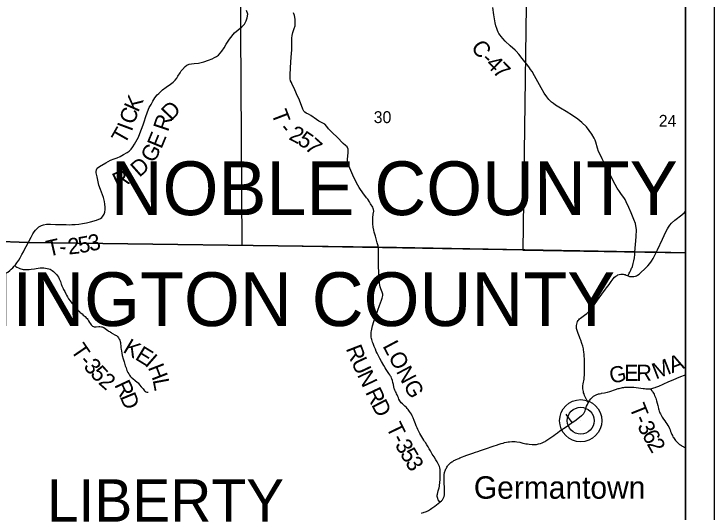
# Model space of a CAD drawing. Extents: x 0 to 34, y 0 to 22.
# Drawn here: x 6.533 to 9, y 15.933 to 17.691 of the extents above; entities that cross this region are included whole.
import ezdxf

# ---------------------------------------------------------------- set-up
doc = ezdxf.new("R2010")
doc.units = 0
for name, color, linetype in [('GM_X_Corporation', 7, 'Continuous'), ('GM_X_County_Road', 7, 'Continuous'), ('GM_X_County_Road_Text', 7, 'Continuous'), ('GM_X_County_Text', 7, 'Continuous'), ('GM_X_Section_Text', 7, 'Continuous'), ('GM_X_Township_Road', 7, 'Continuous'), ('GM_X_Township_Road_Text', 7, 'Continuous'), ('GM_X_Township_Text', 7, 'Continuous'), ('GM_X_Unincorporated', 7, 'Continuous'), ('GM_X_Unincorporated_Location', 7, 'Continuous'), ('GM_X_Unincorporated_Text', 7, 'Continuous'), ('SH_Data', 7, 'Continuous')]:
    doc.layers.add(name, color=color, linetype=linetype)

msp = doc.modelspace()

# ---------------------------------------------------------------- linework, layer by layer
at = {"layer": 'GM_X_Corporation'}
for points in [[(8.3394, 17.8082), (8.3265, 16.8592), (7.3376, 16.8759), (7.332, 17.8222)], [(8.9, 16.8493), (8.9, 17.8023), (8.3394, 17.8082), (8.3265, 16.8592)]]:
    msp.add_lwpolyline(points, close=True, dxfattribs=at)
msp.add_lwpolyline([(8.9, 14.1), (8.9, 16.8499), (8.7964, 16.8516), (8.7214, 16.8529), (7.8171, 16.8691), (6.5825, 16.8858), (6.4571, 16.891), (6.4525, 17.3965), (6.1753, 17.3961), (5.7441, 17.4015), (5.3204, 17.3974), (4.9935, 17.4026), (4.6584, 17.4085), (4.4004, 17.4134)], dxfattribs=at)
at = {"layer": 'GM_X_County_Road'}
for points in [[(8.7216, 16.8524), (8.7258, 16.9063), (8.7264, 16.9317), (8.725, 16.9446), (8.7232, 16.9525), (8.7179, 16.9677), (8.7082, 16.9904), (8.6997, 17.0094), (8.691, 17.0299), (8.6866, 17.0377), (8.6819, 17.0444), (8.6737, 17.0557), (8.6668, 17.0657), (8.6593, 17.0778), (8.6522, 17.0906), (8.6227, 17.148), (8.6152, 17.1626), (8.6057, 17.1811), (8.5984, 17.1957), (8.5935, 17.2066), (8.5899, 17.2183), (8.5834, 17.2399), (8.5809, 17.247), (8.5776, 17.2534), (8.5696, 17.2681), (8.5606, 17.2813), (8.5507, 17.2934), (8.5346, 17.3091), (8.5197, 17.3212), (8.5013, 17.3335), (8.4793, 17.3472), (8.4585, 17.3599), (8.4411, 17.3705), (8.4342, 17.3757), (8.4278, 17.381), (8.4181, 17.3905), (8.4104, 17.3998), (8.4014, 17.4124), (8.3909, 17.4307), (8.3669, 17.4735), (8.3593, 17.4883), (8.3537, 17.4958), (8.3495, 17.5019), (8.3439, 17.5093), (8.3399, 17.5149), (8.3337, 17.5225), (8.3242, 17.5347), (8.3121, 17.5497), (8.3031, 17.5603), (8.2995, 17.5641), (8.2813, 17.5797), (8.2645, 17.5953), (8.2554, 17.6051), (8.2496, 17.6115), (8.246, 17.6166), (8.2423, 17.6228), (8.24, 17.627), (8.2368, 17.6337), (8.2343, 17.6397), (8.2313, 17.6493), (8.2287, 17.6602), (8.2263, 17.674), (8.2241, 17.6888), (8.2208, 17.7147)], [(8.7966, 16.8511), (8.8009, 16.8597), (8.8183, 16.8978), (8.8307, 16.9239), (8.8357, 16.9339), (8.8391, 16.9396), (8.844, 16.9469), (8.8502, 16.9541), (8.8619, 16.9647), (8.8868, 16.984), (8.8955, 16.9915), (8.9, 16.9965)], [(8.6973, 16.7684), (8.6977, 16.7693), (8.7016, 16.7783), (8.7031, 16.7819), (8.7053, 16.7865), (8.7066, 16.7891), (8.7083, 16.7922), (8.7098, 16.7951), (8.7111, 16.7976), (8.7125, 16.8013), (8.7133, 16.8035), (8.714, 16.8059), (8.7157, 16.8118), (8.718, 16.8221), (8.7197, 16.8325), (8.7207, 16.8436), (8.7216, 16.8524)], [(8.6973, 16.7684), (8.7027, 16.7669), (8.7081, 16.7662), (8.7136, 16.7661), (8.7178, 16.7665), (8.7231, 16.7677), (8.7271, 16.7691), (8.7303, 16.7708), (8.7358, 16.7747), (8.7424, 16.7802), (8.7564, 16.7934), (8.7663, 16.8036), (8.7739, 16.8125), (8.7794, 16.82), (8.7857, 16.8299), (8.7917, 16.8414), (8.7966, 16.8511)], [(8.5568, 16.3217), (8.5551, 16.3242), (8.5518, 16.3301), (8.5479, 16.3373), (8.546, 16.3418), (8.544, 16.3467), (8.5421, 16.3524), (8.5407, 16.3569), (8.5396, 16.3612), (8.5387, 16.3654), (8.538, 16.3708), (8.538, 16.376), (8.5382, 16.3816), (8.5391, 16.3885), (8.5419, 16.405), (8.5428, 16.4111), (8.5433, 16.4173), (8.5436, 16.4227), (8.544, 16.4284), (8.5441, 16.4445), (8.5433, 16.4712), (8.5424, 16.4904), (8.5413, 16.5015), (8.5406, 16.507), (8.5397, 16.5118), (8.5387, 16.516), (8.5376, 16.5208), (8.5348, 16.5297), (8.5302, 16.5418), (8.528, 16.5471), (8.5255, 16.5533), (8.5209, 16.5655), (8.5174, 16.5762), (8.5159, 16.583), (8.5154, 16.5887), (8.5154, 16.5938), (8.5162, 16.5988), (8.5173, 16.6031), (8.5191, 16.6072), (8.5214, 16.6111), (8.5238, 16.614), (8.5262, 16.6167), (8.5296, 16.6197), (8.5432, 16.6295), (8.552, 16.6364), (8.5574, 16.6413), (8.5621, 16.6463), (8.5691, 16.6548), (8.576, 16.6644), (8.5892, 16.6832), (8.6045, 16.7036), (8.6178, 16.7215), (8.621, 16.726), (8.63, 16.7386), (8.6374, 16.7487), (8.6447, 16.758), (8.6497, 16.7636), (8.654, 16.7673), (8.6583, 16.7701), (8.6617, 16.7718), (8.6659, 16.7732), (8.6715, 16.7744), (8.6766, 16.7749), (8.6802, 16.7748), (8.6837, 16.7739), (8.6866, 16.7728), (8.69, 16.7711), (8.6973, 16.7684)], [(8.7758, 16.3708), (8.7809, 16.3717), (8.7844, 16.3723), (8.7881, 16.3735), (8.7921, 16.375), (8.7956, 16.3762), (8.8054, 16.3801), (8.8213, 16.387), (8.8412, 16.3958), (8.8566, 16.4025), (8.8686, 16.4077), (8.8829, 16.4138), (8.8957, 16.4187), (8.9, 16.4202)], [(8.5568, 16.3217), (8.5573, 16.3227), (8.5613, 16.3291), (8.5663, 16.3356), (8.5707, 16.3401), (8.5756, 16.3441), (8.5797, 16.347), (8.5842, 16.3494), (8.5873, 16.3508), (8.5901, 16.3517), (8.5927, 16.3525), (8.5964, 16.3532), (8.6019, 16.3545), (8.6039, 16.3548)], [(8.6039, 16.3548), (8.6139, 16.3567), (8.6192, 16.3576), (8.6251, 16.3592), (8.6324, 16.3613), (8.6403, 16.3637), (8.6464, 16.3658), (8.6534, 16.3681), (8.6627, 16.3712), (8.6658, 16.3721), (8.6699, 16.3731), (8.6741, 16.3739), (8.6778, 16.3746), (8.6826, 16.3753), (8.686, 16.3758), (8.6897, 16.3762), (8.6958, 16.3767), (8.701, 16.3768), (8.7059, 16.3768), (8.7177, 16.3759), (8.7344, 16.3739), (8.7504, 16.3716), (8.7553, 16.3711), (8.7602, 16.3705), (8.7676, 16.3702), (8.7749, 16.3707), (8.7758, 16.3708)], [(8.5003, 16.2515), (8.506, 16.2557), (8.5141, 16.2618), (8.5334, 16.2763), (8.5356, 16.278), (8.5379, 16.2804), (8.5396, 16.2821), (8.5415, 16.2844), (8.5426, 16.2861), (8.544, 16.2887), (8.545, 16.2906), (8.5459, 16.2931), (8.5488, 16.3019), (8.5511, 16.309), (8.5537, 16.3154), (8.5568, 16.3217)], [(8.0338, 15.9707), (8.0352, 15.9718), (8.0397, 15.9759), (8.0429, 15.9796), (8.0445, 15.9816), (8.0456, 15.9835), (8.0469, 15.9859), (8.0479, 15.9885), (8.0487, 15.9908), (8.0494, 15.9934), (8.0499, 15.9961), (8.0501, 15.9985), (8.0505, 16.0015), (8.0505, 16.0095), (8.0501, 16.0201), (8.049, 16.0405), (8.0488, 16.0461), (8.0486, 16.0536), (8.0489, 16.0636), (8.0492, 16.067), (8.0497, 16.0705), (8.0499, 16.0728), (8.0505, 16.0759), (8.0514, 16.0791), (8.0524, 16.0817), (8.0537, 16.0848), (8.0554, 16.0885), (8.0568, 16.0915), (8.0587, 16.0946), (8.0606, 16.0977), (8.0625, 16.1003), (8.0642, 16.1022), (8.0663, 16.1046), (8.0681, 16.1065), (8.0704, 16.1085), (8.0729, 16.1106), (8.0759, 16.1127), (8.0791, 16.1149), (8.0833, 16.1174), (8.0872, 16.1195), (8.0917, 16.1217), (8.0968, 16.1238), (8.1004, 16.1254), (8.1043, 16.1271), (8.1288, 16.1363), (8.1505, 16.144), (8.1601, 16.1474), (8.1681, 16.1502), (8.1768, 16.1532), (8.2015, 16.1616), (8.2151, 16.1661), (8.2257, 16.1697), (8.2337, 16.1724), (8.2433, 16.1757), (8.2505, 16.1778), (8.2565, 16.1794), (8.262, 16.1808), (8.2687, 16.1822), (8.2743, 16.1833), (8.2791, 16.184), (8.2872, 16.1849), (8.2905, 16.1851), (8.2942, 16.185), (8.2992, 16.1847), (8.3054, 16.1839), (8.3152, 16.182), (8.3261, 16.1795), (8.3328, 16.1781), (8.3373, 16.1772), (8.3425, 16.1763), (8.3492, 16.1753), (8.3591, 16.1743), (8.367, 16.1742), (8.3744, 16.1749), (8.3816, 16.1763), (8.3881, 16.1781), (8.3944, 16.1804), (8.4012, 16.1835), (8.4045, 16.1852), (8.4077, 16.187), (8.415, 16.1917), (8.428, 16.2011), (8.435, 16.2061), (8.4419, 16.2111), (8.4484, 16.2157), (8.4572, 16.222), (8.4793, 16.2369), (8.4972, 16.2492), (8.5003, 16.2515)], [(7.9689, 15.9328), (7.9718, 15.9334), (7.9759, 15.9346), (7.979, 15.9355), (7.9829, 15.9369), (7.9863, 15.9384), (7.9895, 15.9398), (7.9935, 15.9419), (7.9972, 15.9439), (8.001, 15.9462), (8.0058, 15.9494), (8.0097, 15.9521), (8.0162, 15.957), (8.022, 15.9614), (8.0284, 15.9664), (8.0338, 15.9707)]]:
    msp.add_lwpolyline(points, dxfattribs=at)
at = {"layer": 'GM_X_Township_Road'}
for points in [[(6.5827, 16.8853), (6.5853, 16.8891), (6.5933, 16.9046), (6.5997, 16.9161), (6.6043, 16.9235), (6.6092, 16.9299), (6.6144, 16.9356), (6.6211, 16.9413), (6.6256, 16.9441), (6.6303, 16.9465), (6.6374, 16.9487), (6.6478, 16.9504), (6.6614, 16.9507), (6.6798, 16.95), (6.7002, 16.9498), (6.717, 16.9491), (6.7278, 16.9489), (6.7373, 16.9491), (6.7483, 16.9493), (6.7613, 16.9507), (6.775, 16.9525), (6.7891, 16.9556), (6.8032, 16.9588), (6.8235, 16.9644), (6.8378, 16.9703), (6.8424, 16.9739), (6.8467, 16.9784), (6.8514, 16.9856), (6.8532, 16.9935), (6.8541, 17.0025), (6.8541, 17.0105), (6.8539, 17.021), (6.8525, 17.0303), (6.8486, 17.0443), (6.8375, 17.0732), (6.8321, 17.0887), (6.8288, 17.1056), (6.8261, 17.1176), (6.8238, 17.1271), (6.8229, 17.1318), (6.8224, 17.1367), (6.8237, 17.1425), (6.8264, 17.1475), (6.8346, 17.1537), (6.8573, 17.1671), (6.8733, 17.1758), (6.8859, 17.1808), (6.8968, 17.1847), (6.9074, 17.1895), (6.9192, 17.1958), (6.9325, 17.2033), (6.9396, 17.2085), (6.9465, 17.2153), (6.9524, 17.2232), (6.9581, 17.2325), (6.9716, 17.2573), (6.9769, 17.2701), (6.9881, 17.3009), (6.9929, 17.3143), (6.9965, 17.3271), (7.0035, 17.3467), (7.0101, 17.3615), (7.0161, 17.3725), (7.0224, 17.3836), (7.0292, 17.3963), (7.0374, 17.406), (7.0431, 17.4117), (7.0571, 17.4236), (7.0692, 17.4333), (7.0852, 17.4446), (7.0938, 17.4514), (7.1011, 17.4584), (7.1067, 17.4658), (7.111, 17.4719), (7.1184, 17.484), (7.1227, 17.4906), (7.127, 17.4959), (7.1363, 17.5062), (7.142, 17.5109), (7.1501, 17.5146), (7.1587, 17.5163), (7.1678, 17.5171), (7.1836, 17.5182), (7.1924, 17.5199), (7.2027, 17.5228), (7.2185, 17.5283), (7.231, 17.5337), (7.2393, 17.5379), (7.2465, 17.542), (7.2535, 17.5467), (7.2656, 17.56), (7.2744, 17.5726), (7.2808, 17.5846), (7.2925, 17.6031), (7.3104, 17.6244), (7.3357, 17.6457), (7.345, 17.6556), (7.351, 17.6675), (7.355, 17.6781), (7.3568, 17.6909), (7.3528, 17.7037)], [(7.8173, 16.8686), (7.8162, 16.8743), (7.8134, 16.8846), (7.8069, 16.9082), (7.8029, 16.9223), (7.8015, 16.9296), (7.7994, 16.9398), (7.7978, 16.952), (7.798, 16.9729), (7.7994, 16.9858), (7.8012, 16.9963), (7.8005, 17.002), (7.7995, 17.0065), (7.7975, 17.0107), (7.7901, 17.0222), (7.7856, 17.0294), (7.7804, 17.0383), (7.7759, 17.0441), (7.769, 17.0513), (7.7643, 17.0574), (7.7496, 17.0795), (7.7401, 17.0963), (7.7272, 17.1239), (7.7134, 17.1558), (7.7106, 17.1632), (7.7089, 17.1688), (7.7086, 17.1737), (7.7087, 17.1788), (7.7102, 17.1917), (7.7111, 17.2022), (7.7112, 17.2095), (7.7108, 17.2152), (7.7076, 17.2227), (7.702, 17.2283), (7.6935, 17.2349), (7.6723, 17.2568), (7.6555, 17.2726), (7.6485, 17.2796), (7.6418, 17.2869), (7.6355, 17.2954), (7.6288, 17.3031), (7.6219, 17.3072), (7.6143, 17.3107), (7.6078, 17.3141), (7.5994, 17.3193), (7.5798, 17.3333), (7.5707, 17.3388), (7.563, 17.3419), (7.5576, 17.3449), (7.5543, 17.3491), (7.5513, 17.3565), (7.5389, 17.3874), (7.5292, 17.4099), (7.52, 17.4304), (7.5139, 17.443), (7.5106, 17.4495), (7.5082, 17.4563), (7.5067, 17.4632), (7.5062, 17.4696), (7.507, 17.478), (7.5085, 17.5228), (7.5111, 17.553), (7.512, 17.5639), (7.5122, 17.5862), (7.512, 17.6063), (7.5134, 17.616), (7.5164, 17.6265), (7.521, 17.6402), (7.5235, 17.6496), (7.5244, 17.6591), (7.5236, 17.6733), (7.5213, 17.6865), (7.5187, 17.6949)], [(6.536, 16.8045), (6.5386, 16.8076), (6.5433, 16.814), (6.5497, 16.8237), (6.5552, 16.8326), (6.5611, 16.8433), (6.5664, 16.8538), (6.5714, 16.8637), (6.5756, 16.872), (6.5827, 16.8853)], [(8.0338, 15.9707), (8.0323, 15.9732), (8.0281, 15.9798), (8.0264, 15.9837), (8.0254, 15.9873), (8.0248, 15.9915), (8.0248, 15.9952), (8.0254, 15.9994), (8.0268, 16.0056), (8.0285, 16.0114), (8.0312, 16.0222), (8.0324, 16.0271), (8.0332, 16.0319), (8.0339, 16.0381), (8.0344, 16.0432), (8.0347, 16.0492), (8.035, 16.0647), (8.035, 16.074), (8.0351, 16.0802), (8.0346, 16.087), (8.0342, 16.0899), (8.0335, 16.0925), (8.0322, 16.0966), (8.0302, 16.101), (8.0288, 16.104), (8.0243, 16.1128), (8.0194, 16.1208), (8.0135, 16.1304), (8.0073, 16.1403), (8.0006, 16.152), (7.9967, 16.1586), (7.9925, 16.1659), (7.988, 16.1736), (7.9833, 16.1809), (7.9803, 16.1851), (7.9774, 16.1897), (7.9739, 16.1953), (7.9702, 16.2012), (7.9638, 16.2125), (7.9608, 16.218), (7.9584, 16.2229), (7.9561, 16.2275), (7.9535, 16.2336), (7.9509, 16.2405), (7.9481, 16.2475), (7.9435, 16.2594), (7.94, 16.2684), (7.9367, 16.2757), (7.9336, 16.2811), (7.9303, 16.2862), (7.9272, 16.2903), (7.9247, 16.2938), (7.9217, 16.2977), (7.9188, 16.3012), (7.9161, 16.3044), (7.9108, 16.3096), (7.9057, 16.314), (7.9018, 16.3171), (7.8978, 16.321), (7.8951, 16.3243), (7.8925, 16.3285), (7.8899, 16.3341), (7.8879, 16.3386), (7.886, 16.3438), (7.884, 16.3488), (7.8817, 16.3534), (7.8797, 16.3574), (7.8778, 16.3605), (7.8751, 16.3661), (7.8739, 16.3692), (7.873, 16.3718), (7.8714, 16.3778), (7.8703, 16.3855), (7.8688, 16.3931), (7.8671, 16.3998), (7.8651, 16.4056), (7.8638, 16.4085), (7.8619, 16.4124), (7.8598, 16.4156), (7.8578, 16.4193), (7.8539, 16.425), (7.849, 16.4321), (7.8452, 16.4382), (7.8417, 16.4439), (7.8367, 16.4527), (7.8286, 16.4669), (7.8228, 16.4772), (7.8176, 16.487), (7.8129, 16.4965), (7.81, 16.5026), (7.8069, 16.5101), (7.8028, 16.5193), (7.7984, 16.5308), (7.7967, 16.5353), (7.7951, 16.5402), (7.7937, 16.5443), (7.793, 16.548), (7.7922, 16.552), (7.7918, 16.5553), (7.7914, 16.5612), (7.7916, 16.5665), (7.7921, 16.5698), (7.7927, 16.5751), (7.794, 16.5806), (7.7968, 16.5927), (7.8013, 16.6082), (7.808, 16.6282), (7.8151, 16.6479), (7.8211, 16.6638), (7.8285, 16.6829), (7.83, 16.6865), (7.8312, 16.6905), (7.8321, 16.6947), (7.8327, 16.6997), (7.8326, 16.704), (7.8319, 16.7077), (7.8309, 16.7106), (7.8286, 16.7166), (7.8263, 16.7227), (7.8236, 16.7302), (7.8222, 16.7356), (7.8209, 16.743), (7.8201, 16.7529), (7.8197, 16.7646), (7.8193, 16.7755), (7.819, 16.7845), (7.8179, 16.7993), (7.8175, 16.8105), (7.8175, 16.8223), (7.8176, 16.8302), (7.8177, 16.8397), (7.818, 16.8494), (7.8181, 16.8557), (7.8178, 16.8647), (7.8173, 16.8686)], [(6.4611, 16.7481), (6.4616, 16.7491), (6.4619, 16.7497), (6.4647, 16.7537), (6.4675, 16.7567), (6.4704, 16.7591), (6.4743, 16.7617), (6.4797, 16.7648), (6.4875, 16.769), (6.4976, 16.7741), (6.5111, 16.7819), (6.519, 16.7874), (6.5238, 16.7917), (6.5291, 16.7969), (6.5342, 16.8023), (6.536, 16.8045)], [(6.536, 16.8045), (6.5402, 16.8017), (6.5438, 16.7993), (6.5486, 16.7968), (6.5541, 16.7943), (6.5575, 16.7931), (6.5617, 16.792), (6.566, 16.7914), (6.5715, 16.7911), (6.5796, 16.7911), (6.587, 16.7914), (6.5938, 16.7921), (6.6049, 16.7937), (6.6116, 16.7949), (6.6184, 16.796), (6.6251, 16.7966), (6.6319, 16.7968), (6.6387, 16.7966), (6.6442, 16.7959), (6.6503, 16.7947), (6.6563, 16.7931), (6.6603, 16.7916), (6.6642, 16.7897), (6.6679, 16.7875), (6.6724, 16.7841), (6.6762, 16.7809), (6.6797, 16.7774), (6.6833, 16.7731), (6.6869, 16.7681), (6.6899, 16.7635), (6.6929, 16.7582), (6.6949, 16.7538), (6.6966, 16.7492), (6.6985, 16.7435), (6.6998, 16.7393), (6.7008, 16.7364), (6.7022, 16.733), (6.7031, 16.7306), (6.7063, 16.7239), (6.708, 16.7206), (6.7119, 16.7129), (6.7157, 16.705), (6.7181, 16.7), (6.7212, 16.6946), (6.7256, 16.6879), (6.7309, 16.6803), (6.7372, 16.6719), (6.7428, 16.6648), (6.7475, 16.6592), (6.7532, 16.6531), (6.7587, 16.6475), (6.7649, 16.6417), (6.7667, 16.64), (6.7729, 16.635), (6.7774, 16.6306), (6.784, 16.6249), (6.7881, 16.6211), (6.791, 16.6179), (6.7932, 16.6149), (6.7961, 16.6101), (6.7995, 16.6042), (6.8026, 16.5996), (6.8053, 16.5962), (6.8078, 16.5935), (6.8102, 16.5916), (6.8129, 16.5901), (6.8158, 16.589), (6.8188, 16.5886), (6.8225, 16.5887), (6.8318, 16.5898), (6.8362, 16.5898), (6.8411, 16.5894), (6.8435, 16.5889), (6.8464, 16.5878), (6.8497, 16.5861), (6.8543, 16.583), (6.8643, 16.5756), (6.8663, 16.5742), (6.8695, 16.5722), (6.8716, 16.571), (6.8726, 16.5702), (6.8753, 16.5687), (6.878, 16.5671), (6.891, 16.56), (6.8942, 16.558), (6.8965, 16.556), (6.899, 16.5533), (6.9012, 16.5503), (6.9037, 16.546), (6.9058, 16.5416), (6.9073, 16.5376), (6.9082, 16.5341), (6.9089, 16.5293), (6.9094, 16.5219), (6.9097, 16.5152), (6.9104, 16.5103), (6.9116, 16.5035), (6.9132, 16.4956), (6.915, 16.4878), (6.918, 16.4764), (6.921, 16.4657), (6.9252, 16.4521), (6.928, 16.4439), (6.9314, 16.4353), (6.9345, 16.4286), (6.9374, 16.4231), (6.9401, 16.419), (6.9431, 16.4151), (6.9465, 16.4116), (6.9515, 16.407), (6.9607, 16.3996), (6.9674, 16.3941), (6.9706, 16.3911), (6.976, 16.3851), (6.9818, 16.3779), (6.9879, 16.3699), (6.9929, 16.3636), (6.9952, 16.3615), (6.9967, 16.3605), (6.9984, 16.3597), (7.0008, 16.3592), (7.0045, 16.3586), (7.0057, 16.3585)], [(8.7758, 16.3708), (8.7778, 16.3683), (8.7811, 16.364), (8.7829, 16.3614), (8.785, 16.3585), (8.7871, 16.355), (8.7889, 16.3514), (8.7908, 16.3475), (8.7919, 16.3444), (8.793, 16.3421), (8.7945, 16.3378), (8.7962, 16.3334), (8.7977, 16.3282), (8.8, 16.3199), (8.8019, 16.3122), (8.803, 16.3069), (8.8047, 16.3005), (8.8056, 16.2969), (8.807, 16.2923), (8.808, 16.2896), (8.8095, 16.2861), (8.811, 16.2826), (8.8127, 16.2795), (8.8146, 16.2759), (8.8175, 16.2711), (8.8197, 16.2674), (8.8224, 16.2632), (8.8263, 16.2576), (8.8304, 16.2515), (8.8339, 16.2466), (8.8376, 16.2414), (8.8408, 16.2361), (8.8434, 16.2305), (8.8453, 16.2257), (8.8468, 16.2205), (8.8487, 16.2152), (8.8515, 16.209), (8.8532, 16.2057), (8.8553, 16.2019), (8.8572, 16.1985), (8.8596, 16.1951), (8.8615, 16.1923), (8.8647, 16.188), (8.8685, 16.184), (8.8709, 16.1813), (8.8741, 16.1785), (8.8762, 16.1768), (8.8788, 16.1747), (8.8817, 16.1727), (8.885, 16.1703), (8.8875, 16.1687), (8.8909, 16.1668), (8.8927, 16.1659), (8.8948, 16.165), (8.8968, 16.1644), (8.8993, 16.1637), (8.9, 16.1635)], [(8.5003, 16.2515), (8.4997, 16.2523), (8.4903, 16.2646), (8.4872, 16.2691), (8.4829, 16.2752), (8.479, 16.2807)]]:
    msp.add_lwpolyline(points, dxfattribs=at)
at = {"layer": 'GM_X_Township_Text'}
for points in [[(8.9, 16.8499), (8.9, 20.9), (6.4827, 20.9)], [(4.4004, 17.4134), (4.6584, 17.4085), (4.9935, 17.4026), (5.3204, 17.3974), (5.7441, 17.4015), (6.1753, 17.3961), (6.4525, 17.3965), (6.4571, 16.891), (6.5825, 16.8858), (7.8171, 16.8691), (8.7214, 16.8529), (8.7964, 16.8516), (8.9, 16.8499)], [(6.4571, 16.891), (6.446, 16.7493), (6.4489, 16.4198), (6.4561, 16.2366), (6.4452, 15.3843), (6.4323, 14.1), (8.9, 14.1), (8.9, 16.8499)]]:
    msp.add_lwpolyline(points, dxfattribs=at)
at = {"layer": 'GM_X_Unincorporated'}
for radius in [0.0744, 0.0472]:
    msp.add_circle((8.5303, 16.2582), radius, dxfattribs=at)
at = {"layer": 'GM_X_Unincorporated_Location'}
msp.add_line((8.5303, 16.2582), (8.5303, 16.2582), dxfattribs=at)
at = {"layer": 'SH_Data'}
for p, q in [((9, 21), (9, 14)), ((8.9, 20.9), (8.9, 14.1))]:
    msp.add_line(p, q, dxfattribs=at)

# ---------------------------------------------------------------- texts
at = {"layer": 'GM_X_County_Road_Text'}
for s, rotation, p in [('C', 305.1656, (8.1415, 17.5749)), ('-', 315.9062, (8.176, 17.528)), ('4', 315.4305, (8.1926, 17.5118)), ('7', 314.5731, (8.2174, 17.4874)), ('A', 21.0336, (8.8524, 16.4254)), ('E', 0.06, (8.6834, 16.3983)), ('R', 0.5745, (8.7265, 16.3984)), ('M', 21.2453, (8.795, 16.4031)), ('G', 12.3388, (8.6378, 16.388))]:
    msp.add_text(s, height=0.0568, rotation=rotation, dxfattribs=at).set_placement(p)
at = {"layer": 'GM_X_County_Text'}
for s, p in [('NOBLE COUNTY', (6.8739, 16.9825)), ('WASHINGTON COUNTY', (5.7674, 16.5917))]:
    msp.add_text(s, height=0.189394, dxfattribs=at).set_placement(p)
at = {"layer": 'GM_X_Section_Text'}
for s, p in [('30', (7.8008, 17.3069)), ('24', (8.8053, 17.2939))]:
    msp.add_text(s, height=0.04186, rotation=0, dxfattribs=at).set_placement(p)
at = {"layer": 'GM_X_Township_Road_Text'}
for s, height, rotation, p in [('K', 0.0568, 66.026, (6.9707, 17.3423)), ('D', 0.0568, 46.3679, (7.0876, 17.3126)), ('C', 0.0568, 71.9979, (6.9568, 17.2994)), ('T', 0.0568, 290.8575, (7.439, 17.3417)), ('R', 0.0568, 71.2281, (7.0759, 17.274)), ('T', 0.0568, 60.5916, (6.9228, 17.2292)), ('I', 0.0568, 69.5138, (6.9478, 17.275)), ('-', 0.0568, 309.7066, (7.4643, 17.2845)), ('2', 0.0568, 332.789, (7.4986, 17.251)), ('E', 0.0568, 67.5914, (7.0527, 17.2135)), ('5', 0.0568, 325.8394, (7.5281, 17.236)), ('7', 0.0568, 317.9451, (7.5554, 17.2176)), ('G', 0.0568, 61.2786, (7.0257, 17.1635)), ('D', 0.0568, 41.5116, (6.975, 17.1137)), ('I', 0.0568, 27.4269, (6.9418, 17.0943)), ('R', 0.0568, 25.0864, (6.8972, 17.0734)), ('T', 0.0568, 12.9011, (6.6543, 16.8358)), ('2', 0.0568, 6.1608, (6.7255, 16.8435)), ('5', 0.0568, 10.0444, (6.7644, 16.8479)), ('3', 0.0568, 12.3046, (6.8013, 16.8545)), ('-', 0.0568, 356.1018, (6.6913, 16.8449)), ('T', 0.0568, 304.3569, (6.7313, 16.5064)), ('K', 0.0568, 329.323, (6.914, 16.5016)), ('R', 0.0568, 291.1549, (7.7018, 16.5126)), ('LONG', 0.05682, 297.8588, (7.8311, 16.5216)), ('E', 0.0568, 328.5166, (6.9568, 16.4762)), ('-', 0.0568, 310.7667, (6.7596, 16.4658)), ('I', 0.0568, 318.7451, (6.991, 16.4555)), ('U', 0.0568, 295.1026, (7.7203, 16.4652)), ('3', 0.0568, 312.0621, (6.7757, 16.4471)), ('5', 0.0568, 312.3605, (6.7994, 16.4208)), ('H', 0.0568, 291.1453, (7.0044, 16.446)), ('N', 0.0568, 295.1561, (7.7415, 16.4199)), ('2', 0.0568, 318.6934, (6.8278, 16.3902)), ('L', 0.0568, 280.6644, (7.0217, 16.402)), ('R', 0.0568, 295.0131, (6.8858, 16.3847)), ('D', 0.0568, 292.5036, (6.9053, 16.343)), ('R', 0.0568, 295.217, (7.7702, 16.3588)), ('D', 0.0568, 297.3139, (7.7911, 16.3145)), ('T', 0.0568, 291.9705, (8.7007, 16.3056)), ('T', 0.0568, 295.7198, (7.8435, 16.2356)), ('3', 0.0568, 297.7959, (8.7282, 16.2393)), ('-', 0.0568, 292.9483, (8.7169, 16.2653)), ('6', 0.0568, 298.68, (8.7448, 16.2077)), ('3', 0.0568, 299.0879, (7.8743, 16.1734)), ('-', 0.0568, 297.4802, (7.8627, 16.1956)), ('2', 0.0568, 299.7137, (8.762, 16.1763)), ('5', 0.0568, 300.4226, (7.8921, 16.1415)), ('3', 0.0568, 301.1229, (7.9102, 16.1107))]:
    msp.add_text(s, height=height, rotation=rotation, dxfattribs=at).set_placement(p)
at = {"layer": 'GM_X_Township_Text'}
msp.add_text('LIBERTY', height=0.15, rotation=0, dxfattribs=at).set_placement((6.6491, 15.9021))
at = {"layer": 'GM_X_Unincorporated_Text'}
msp.add_text('Germantown', height=0.07898, rotation=0, dxfattribs=at).set_placement((8.1537, 15.9833))

doc.saveas('drawing.dxf')
